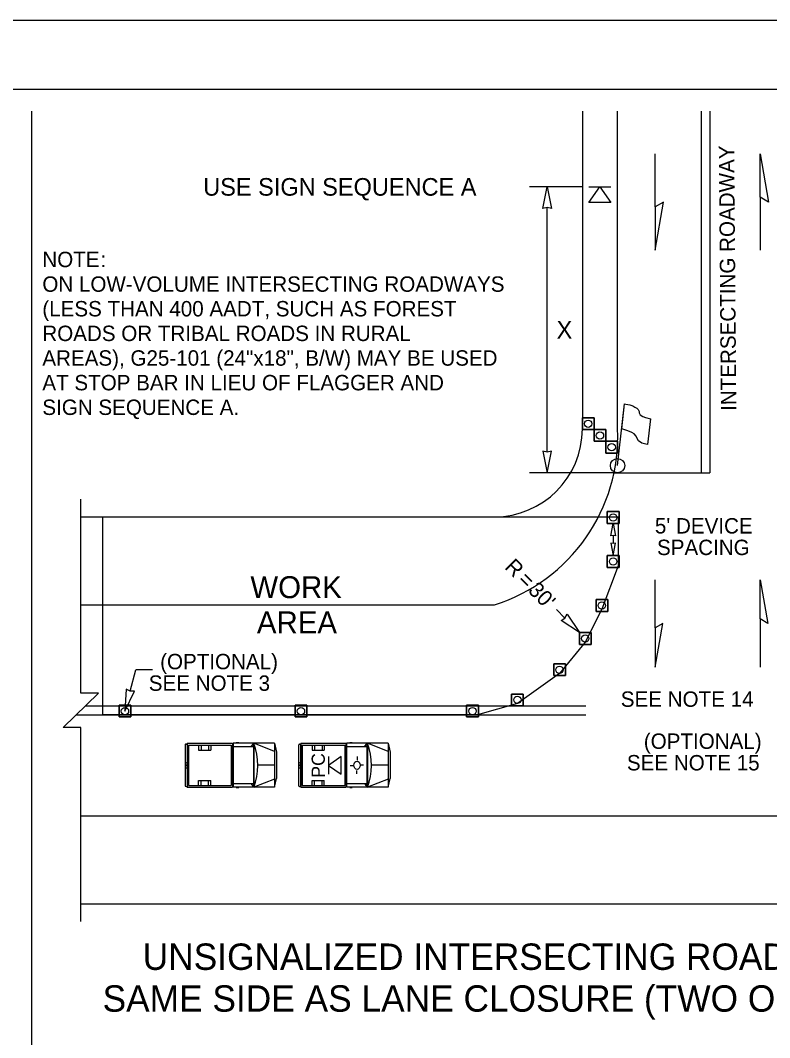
# Model space of a CAD drawing. Extents: x 99999.1 to 100095.7, y 99995 to 100010.7.
# Drawn here: x 100025.2 to 100028.607, y 100006.062 to 100010.687 of the extents above; entities that cross this region are included whole.
import ezdxf

# ---------------------------------------------------------------- set-up
doc = ezdxf.new("R2010")
doc.units = 0
for name, color, linetype in [('RD_ED_ShoulderPavedEdge', 7, 'Continuous'), ('RD_MK_LineDblYellowCenter', 7, 'Continuous'), ('RD_MK_LineEdgeWhite', 7, 'Continuous'), ('RD_MK_LineStop', 7, 'Continuous'), ('SH_DE_DetailBody1Text', 7, 'Continuous'), ('SH_DE_DetailHeading2Text', 7, 'Continuous'), ('SH_GI_PlotLimits', 7, 'Continuous'), ('SH_GI_SheetBorder', 7, 'Continuous'), ('TR_WZ_FlaggingStation', 7, 'Continuous'), ('TR_WZ_MotoristVehicle', 7, 'Continuous'), ('TR_WZ_PortableSignMountBlk-Org', 7, 'Continuous'), ('TR_WZ_PortableSignMountBlk-Wht', 7, 'Continuous'), ('TR_WZ_TrafficCone', 7, 'Continuous'), ('TR_WZ_WorkAreaLabel', 7, 'Continuous'), ('TR_WZ_WorkZoneDetails', 7, 'Continuous'), ('TR_WZ_WorkZoneTextCurrent', 7, 'Continuous')]:
    doc.layers.add(name, color=color, linetype=linetype)

msp = doc.modelspace()

# ---------------------------------------------------------------- linework, layer by layer
at = {"layer": 'RD_ED_ShoulderPavedEdge'}
for p, q in [((100025.475, 100008.4304), (100027.355, 100008.4304)), ((100025.475, 100006.6704), (100030.275, 100006.6704))]:
    msp.add_line(p, q, dxfattribs=at)
msp.add_lwpolyline([(100027.755, 100010.275), (100027.755, 100008.8304)], dxfattribs=at)
msp.add_arc((100027.355, 100008.8304), 0.4, 270, 0, dxfattribs=at)
at = {"layer": 'RD_MK_LineDblYellowCenter'}
for p, q in [((100028.295, 100010.275), (100028.295, 100008.6304)), ((100028.335, 100010.275), (100028.335, 100008.6304)), ((100025.4957, 100007.5704), (100027.7712, 100007.5704)), ((100025.4543, 100007.5305), (100027.7712, 100007.5305))]:
    msp.add_line(p, q, dxfattribs=at)
at = {"layer": 'RD_MK_LineEdgeWhite'}
for p, q in [((100027.915, 100008.8304), (100027.915, 100010.275)), ((100025.475, 100008.0305), (100027.355, 100008.0305)), ((100025.475, 100007.0704), (100030.275, 100007.0704))]:
    msp.add_line(p, q, dxfattribs=at)
msp.add_arc((100027.1158, 100008.7939), 0.8, 287.3948, 2.6212, dxfattribs=at)
at = {"layer": 'RD_MK_LineStop'}
msp.add_line((100027.899, 100008.6304), (100028.335, 100008.6304), dxfattribs=at)
at = {"layer": 'SH_GI_PlotLimits'}
msp.add_lwpolyline([(100019.0625, 99999.6875), (100036.0625, 99999.6875), (100036.0625, 100010.6875), (100019.0625, 100010.6875)], close=True, dxfattribs=at)
at = {"layer": 'SH_GI_SheetBorder'}
msp.add_line((100020, 100010.375), (100035.75, 100010.375), dxfattribs=at)
at = {"layer": 'TR_WZ_FlaggingStation'}
for p, q in [((100027.915, 100008.6629), (100027.9471, 100008.9439)), ((100027.934, 100008.8299), (100027.9471, 100008.9442)), ((100028.065, 100008.8764), (100028.0517, 100008.7592)), ((100027.934, 100008.8299), (100027.934, 100008.8299))]:
    msp.add_line(p, q, dxfattribs=at)
for points in [[(100027.9471, 100008.9442), (100027.9528, 100008.9429), (100027.9707, 100008.9395), (100027.9845, 100008.9353), (100027.9942, 100008.9292), (100028.0027, 100008.9245), (100028.0084, 100008.9177), (100028.0126, 100008.9098), (100028.0131, 100008.9037), (100028.0185, 100008.8944), (100028.0293, 100008.887), (100028.0417, 100008.8818), (100028.065, 100008.8764)], [(100028.0517, 100008.7592), (100028.0436, 100008.7606), (100028.0259, 100008.7653), (100028.0103, 100008.7758), (100028.0037, 100008.7863), (100027.9998, 100008.7966), (100027.9907, 100008.8075), (100027.9798, 100008.8137), (100027.9624, 100008.8208), (100027.934, 100008.8299)]]:
    msp.add_lwpolyline(points, dxfattribs=at)
msp.add_circle((100027.915, 100008.6629), 0.0325, dxfattribs=at)
at = {"layer": 'TR_WZ_MotoristVehicle'}
for p, q in [((100025.9487, 100007.3911), (100025.9487, 100007.2098)), ((100025.9532, 100007.3972), (100025.9577, 100007.3972)), ((100025.9577, 100007.3972), (100025.9577, 100007.2037)), ((100025.9584, 100007.4005), (100026.1641, 100007.4005)), ((100025.9584, 100007.4005), (100025.9584, 100007.2005)), ((100025.9642, 100007.3925), (100025.9642, 100007.2084)), ((100025.9642, 100007.3925), (100026.1582, 100007.3925)), ((100026.0106, 100007.3925), (100026.0106, 100007.3695)), ((100026.0106, 100007.3695), (100026.0655, 100007.3695)), ((100026.0215, 100007.3925), (100026.0215, 100007.3695)), ((100026.0556, 100007.3925), (100026.0556, 100007.3695)), ((100026.0655, 100007.3925), (100026.0655, 100007.3695)), ((100026.1582, 100007.3925), (100026.1582, 100007.2084)), ((100026.1641, 100007.4005), (100026.1641, 100007.2005)), ((100026.1668, 100007.4005), (100026.1668, 100007.2005)), ((100026.3557, 100007.4005), (100026.1668, 100007.4005)), ((100026.2596, 100007.385), (100026.1668, 100007.385)), ((100026.1926, 100007.4033), (100026.1813, 100007.4033)), ((100026.2596, 100007.4005), (100026.2475, 100007.385)), ((100026.2596, 100007.4005), (100026.2596, 100007.2005)), ((100026.2613, 100007.4005), (100026.2613, 100007.2005)), ((100026.3557, 100007.3638), (100026.2613, 100007.4005)), ((100026.3557, 100007.4005), (100026.3557, 100007.2005)), ((100026.3557, 100007.4005), (100026.365, 100007.3601)), ((100026.365, 100007.3601), (100026.365, 100007.2408)), ((100026.465, 100007.3911), (100026.465, 100007.2098)), ((100026.4695, 100007.3972), (100026.4739, 100007.3972)), ((100026.4739, 100007.3972), (100026.4739, 100007.2037)), ((100026.4746, 100007.4005), (100026.6803, 100007.4005)), ((100026.4746, 100007.4005), (100026.4746, 100007.2005)), ((100026.4805, 100007.3925), (100026.4805, 100007.2084)), ((100026.4805, 100007.3925), (100026.6745, 100007.3925)), ((100026.5268, 100007.3925), (100026.5268, 100007.3695)), ((100026.5268, 100007.3695), (100026.5818, 100007.3695)), ((100026.5378, 100007.3925), (100026.5378, 100007.3695)), ((100026.5718, 100007.3925), (100026.5718, 100007.3695)), ((100026.5818, 100007.3925), (100026.5818, 100007.3695)), ((100026.6745, 100007.3925), (100026.6745, 100007.2084)), ((100026.6803, 100007.4005), (100026.6803, 100007.2005)), ((100026.6831, 100007.4005), (100026.6831, 100007.2005)), ((100026.872, 100007.4005), (100026.6831, 100007.4005)), ((100026.7758, 100007.385), (100026.6831, 100007.385)), ((100026.7089, 100007.4033), (100026.6975, 100007.4033)), ((100026.7758, 100007.4005), (100026.7638, 100007.385)), ((100026.7758, 100007.4005), (100026.7758, 100007.2005)), ((100026.7775, 100007.4005), (100026.7775, 100007.2005)), ((100026.872, 100007.3638), (100026.7775, 100007.4005)), ((100026.872, 100007.4005), (100026.872, 100007.2005)), ((100026.872, 100007.4005), (100026.8813, 100007.3601)), ((100026.8813, 100007.3601), (100026.8813, 100007.2408)), ((100025.9487, 100007.3145), (100025.9577, 100007.3108)), ((100026.465, 100007.3145), (100026.4739, 100007.3108)), ((100026.7305, 100007.3401), (100026.7305, 100007.3239)), ((100025.9487, 100007.2864), (100025.9577, 100007.2901)), ((100025.9511, 100007.3005), (100025.9553, 100007.3005)), ((100025.9532, 100007.3033), (100025.9532, 100007.2976)), ((100026.3557, 100007.3005), (100026.2798, 100007.3005)), ((100026.465, 100007.2864), (100026.4739, 100007.2901)), ((100026.4674, 100007.3005), (100026.4715, 100007.3005)), ((100026.4695, 100007.3033), (100026.4695, 100007.2976)), ((100026.6996, 100007.2997), (100026.7145, 100007.3001)), ((100026.7164, 100007.3001), (100026.7164, 100007.3001)), ((100026.7298, 100007.262), (100026.7301, 100007.277)), ((100026.7606, 100007.3006), (100026.748, 100007.3005)), ((100026.872, 100007.3005), (100026.7961, 100007.3005)), ((100026.0106, 100007.2084), (100026.0106, 100007.2314)), ((100026.0106, 100007.2314), (100026.0655, 100007.2314)), ((100026.0215, 100007.2084), (100026.0215, 100007.2314)), ((100026.0556, 100007.2084), (100026.0556, 100007.2314)), ((100026.0655, 100007.2084), (100026.0655, 100007.2314)), ((100026.3557, 100007.2371), (100026.2613, 100007.2005)), ((100026.3557, 100007.2005), (100026.365, 100007.2408)), ((100026.5268, 100007.2084), (100026.5268, 100007.2314)), ((100026.5268, 100007.2314), (100026.5818, 100007.2314)), ((100026.5378, 100007.2084), (100026.5378, 100007.2314)), ((100026.5718, 100007.2084), (100026.5718, 100007.2314)), ((100026.5818, 100007.2084), (100026.5818, 100007.2314)), ((100026.872, 100007.2371), (100026.7775, 100007.2005)), ((100026.872, 100007.2005), (100026.8813, 100007.2408)), ((100025.9532, 100007.2037), (100025.9577, 100007.2037)), ((100025.9584, 100007.2005), (100026.1641, 100007.2005)), ((100025.9642, 100007.2084), (100026.1582, 100007.2084)), ((100026.2596, 100007.216), (100026.1668, 100007.216)), ((100026.3557, 100007.2005), (100026.1668, 100007.2005)), ((100026.1926, 100007.1976), (100026.1813, 100007.1976)), ((100026.2496, 100007.216), (100026.2596, 100007.2005)), ((100026.4695, 100007.2037), (100026.4739, 100007.2037)), ((100026.4746, 100007.2005), (100026.6803, 100007.2005)), ((100026.4805, 100007.2084), (100026.6745, 100007.2084)), ((100026.7758, 100007.216), (100026.6831, 100007.216)), ((100026.872, 100007.2005), (100026.6831, 100007.2005)), ((100026.7089, 100007.1976), (100026.6975, 100007.1976)), ((100026.7659, 100007.216), (100026.7758, 100007.2005))]:
    msp.add_line(p, q, dxfattribs=at)
for centre, major_axis, start_param, end_param in [((100025.9532, 100007.3911), (0, 0.0061), 6.283185, 7.853982), ((100026.1263, 100007.3004), (0, 0.2099), 4.215852, 5.209111), ((100026.4695, 100007.3911), (0, 0.0061), 6.283185, 7.853982), ((100026.6426, 100007.3004), (0, 0.2099), 4.215852, 5.209111), ((100025.9532, 100007.2098), (0, -0.0061), 4.712389, 6.283185), ((100026.4695, 100007.2098), (0, -0.0061), 4.712389, 6.283185)]:
    msp.add_ellipse(centre, major_axis=major_axis, ratio=0.73155, start_param=start_param, end_param=end_param, dxfattribs=at)
for centre, major_axis in [((100026.7305, 100007.3005), (0, -0.0193)), ((100025.9532, 100007.3005), (0, -0.00282)), ((100026.4695, 100007.3005), (0, -0.00282))]:
    msp.add_ellipse(centre, major_axis=major_axis, ratio=0.73155, dxfattribs=at)
at = {"layer": 'TR_WZ_PortableSignMountBlk-Org'}
msp.add_line((100027.785, 100009.9304), (100027.885, 100009.9304), dxfattribs=at)
msp.add_lwpolyline([(100027.8349, 100009.9304), (100027.885, 100009.8586), (100027.785, 100009.8586)], close=True, dxfattribs=at)
at = {"layer": 'TR_WZ_PortableSignMountBlk-Wht'}
msp.add_line((100026.6007, 100007.3404), (100026.6007, 100007.2604), dxfattribs=at)
msp.add_lwpolyline([(100026.6007, 100007.3004), (100026.6581, 100007.2604), (100026.6581, 100007.3404)], close=True, dxfattribs=at)
at = {"layer": 'TR_WZ_TrafficCone'}
for points in [[(100027.8083, 100008.8803), (100027.8083, 100008.827), (100027.755, 100008.827), (100027.755, 100008.8803), (100027.8083, 100008.8803)], [(100027.755, 100008.8803), (100027.755, 100008.827), (100027.8083, 100008.827), (100027.8083, 100008.8803), (100027.755, 100008.8803)], [(100027.8617, 100008.827), (100027.8617, 100008.7736), (100027.8083, 100008.7736), (100027.8083, 100008.827), (100027.8617, 100008.827)], [(100027.8083, 100008.827), (100027.8083, 100008.7736), (100027.8617, 100008.7736), (100027.8617, 100008.827), (100027.8083, 100008.827)], [(100027.915, 100008.7736), (100027.915, 100008.7203), (100027.8617, 100008.7203), (100027.8617, 100008.7736), (100027.915, 100008.7736)], [(100027.8617, 100008.7736), (100027.8617, 100008.7203), (100027.915, 100008.7203), (100027.915, 100008.7736), (100027.8617, 100008.7736)], [(100027.8684, 100008.4538), (100027.9217, 100008.4538), (100027.9217, 100008.4005), (100027.8684, 100008.4005), (100027.8684, 100008.4538)], [(100027.8684, 100008.4005), (100027.9217, 100008.4005), (100027.9217, 100008.4538), (100027.8684, 100008.4538), (100027.8684, 100008.4005)], [(100027.8684, 100008.2538), (100027.9217, 100008.2538), (100027.9217, 100008.2005), (100027.8684, 100008.2005), (100027.8684, 100008.2538)], [(100027.8684, 100008.2005), (100027.9217, 100008.2005), (100027.9217, 100008.2538), (100027.8684, 100008.2538), (100027.8684, 100008.2005)], [(100027.8173, 100008.0538), (100027.8707, 100008.0538), (100027.8707, 100008.0005), (100027.8173, 100008.0005), (100027.8173, 100008.0538)], [(100027.8173, 100008.0005), (100027.8707, 100008.0005), (100027.8707, 100008.0538), (100027.8173, 100008.0538), (100027.8173, 100008.0005)], [(100027.7417, 100007.9038), (100027.795, 100007.9038), (100027.795, 100007.8505), (100027.7417, 100007.8505), (100027.7417, 100007.9038)], [(100027.7417, 100007.8505), (100027.795, 100007.8505), (100027.795, 100007.9038), (100027.7417, 100007.9038), (100027.7417, 100007.8505)], [(100027.6247, 100007.7615), (100027.6781, 100007.7615), (100027.6781, 100007.7082), (100027.6247, 100007.7082), (100027.6247, 100007.7615)], [(100027.6247, 100007.7082), (100027.6781, 100007.7082), (100027.6781, 100007.7615), (100027.6247, 100007.7615), (100027.6247, 100007.7082)], [(100027.433, 100007.6247), (100027.4864, 100007.6247), (100027.4864, 100007.5714), (100027.433, 100007.5714), (100027.433, 100007.6247)], [(100027.433, 100007.5714), (100027.4864, 100007.5714), (100027.4864, 100007.6247), (100027.433, 100007.6247), (100027.433, 100007.5714)], [(100025.649, 100007.5738), (100025.7024, 100007.5738), (100025.7024, 100007.5205), (100025.649, 100007.5205), (100025.649, 100007.5738)], [(100025.649, 100007.5205), (100025.7024, 100007.5205), (100025.7024, 100007.5738), (100025.649, 100007.5738), (100025.649, 100007.5205)], [(100026.449, 100007.5738), (100026.5024, 100007.5738), (100026.5024, 100007.5205), (100026.449, 100007.5205), (100026.449, 100007.5738)], [(100026.449, 100007.5205), (100026.5024, 100007.5205), (100026.5024, 100007.5738), (100026.449, 100007.5738), (100026.449, 100007.5205)], [(100027.229, 100007.5738), (100027.2824, 100007.5738), (100027.2824, 100007.5205), (100027.229, 100007.5205), (100027.229, 100007.5738)], [(100027.229, 100007.5205), (100027.2824, 100007.5205), (100027.2824, 100007.5738), (100027.229, 100007.5738), (100027.229, 100007.5205)]]:
    msp.add_lwpolyline(points, dxfattribs=at)
for centre in [(100027.7817, 100008.8536), (100027.835, 100008.8003), (100027.8883, 100008.747), (100027.895, 100008.4271), (100027.895, 100008.2271), (100027.844, 100008.0271), (100027.7683, 100007.8771), (100027.6514, 100007.7349), (100027.4597, 100007.598), (100025.6757, 100007.5471), (100026.4757, 100007.5471), (100027.2557, 100007.5471)]:
    msp.add_circle(centre, 0.0167, dxfattribs=at)
at = {"layer": 'TR_WZ_WorkZoneDetails'}
for p, q in [((100025.25, 100010.275), (100025.25, 100001.6859)), ((100028.0855, 100009.8393), (100028.0855, 100010.0804)), ((100027.755, 100009.9304), (100027.515, 100009.9304)), ((100028.5627, 100009.8839), (100028.5627, 100009.6428)), ((100027.595, 100008.7242), (100027.595, 100009.8367)), ((100027.899, 100008.6304), (100027.515, 100008.6304)), ((100027.8951, 100008.3459), (100027.8951, 100008.3083)), ((100028.0855, 100007.9255), (100028.0855, 100008.1445)), ((100027.6754, 100007.9701), (100027.637, 100008.0085)), ((100028.5627, 100007.9659), (100028.5627, 100007.7469)), ((100025.6993, 100007.6378), (100025.7245, 100007.7352)), ((100025.8007, 100007.7352), (100025.7245, 100007.7352))]:
    msp.add_line(p, q, dxfattribs=at)
for points in [[(100028.5627, 100010.0804), (100028.6013, 100009.8616), (100028.5627, 100009.8839)], [(100027.595, 100009.9304), (100027.6143, 100009.8322), (100027.595, 100009.8367), (100027.5757, 100009.8322)], [(100028.0855, 100009.6428), (100028.124, 100009.8616), (100028.0855, 100009.8393)], [(100027.595, 100008.6304), (100027.6143, 100008.7287), (100027.595, 100008.7242), (100027.5757, 100008.7287)], [(100027.9183, 100008.4304), (100027.9183, 100008.2071), (100027.844, 100008.0105), (100027.7683, 100007.8605), (100027.7683, 100007.8605), (100027.7683, 100007.8605), (100027.6514, 100007.7182), (100027.6514, 100007.7182), (100027.6514, 100007.7182), (100027.4597, 100007.5814), (100027.279, 100007.5305), (100026.499, 100007.5305), (100025.699, 100007.5305), (100025.575, 100007.5305), (100025.575, 100008.4304)], [(100027.895, 100008.4005), (100027.9063, 100008.3433), (100027.895, 100008.3459), (100027.8838, 100008.3433)], [(100027.8951, 100008.2538), (100027.9063, 100008.3109), (100027.8951, 100008.3083), (100027.8839, 100008.3109)], [(100028.5627, 100008.1445), (100028.5977, 100007.9457), (100028.5627, 100007.9659)], [(100027.7417, 100007.9038), (100027.6586, 100007.9597), (100027.6754, 100007.9701), (100027.6858, 100007.987)], [(100028.0855, 100007.7469), (100028.1205, 100007.9457), (100028.0855, 100007.9255)], [(100025.6757, 100007.5471), (100025.719, 100007.6374), (100025.6992, 100007.6379), (100025.6817, 100007.6471)]]:
    msp.add_lwpolyline(points, close=True, dxfattribs=at)
msp.add_lwpolyline([(100025.475, 100006.5905), (100025.475, 100007.473), (100025.395, 100007.473), (100025.555, 100007.6279), (100025.475, 100007.6279), (100025.475, 100008.5105)], dxfattribs=at)

# ---------------------------------------------------------------- texts
at = {"layer": 'SH_DE_DetailBody1Text'}
msp.add_text('INTERSECTING ROADWAY', height=0.07, rotation=90.4626, dxfattribs=at).set_placement((100028.455, 100008.9122))
at = {"layer": 'SH_DE_DetailHeading2Text'}
for s, p in [('UNSIGNALIZED INTERSECTING ROADWAY DETAIL', (100025.7563, 100006.3705)), ('SAME SIDE AS LANE CLOSURE (TWO OPEN LANES)', (100025.5738, 100006.1804))]:
    msp.add_text(s, height=0.12, rotation=360, dxfattribs=at).set_placement(p)
at = {"layer": 'TR_WZ_MotoristVehicle'}
msp.add_text('PC', height=0.06, rotation=90, dxfattribs=at).set_placement((100026.5843, 100007.2444))
at = {"layer": 'TR_WZ_WorkAreaLabel'}
for s, p in [('WORK', (100026.2458, 100008.0605)), ('AREA', (100026.2754, 100007.9004))]:
    msp.add_text(s, height=0.1, dxfattribs=at).set_placement(p)
at = {"layer": 'TR_WZ_WorkZoneDetails'}
for s, p in [('NOTE', (100025.3, 100009.5654)), (':', (100025.5641, 100009.5654)), ('ON LOW-VOLUME INTERSECTING ROADWAYS ', (100025.3, 100009.4534)), ('(LESS THAN 400 AADT, SUCH AS FOREST ', (100025.3, 100009.3414)), ('ROADS OR TRIBAL ROADS IN RURAL ', (100025.3, 100009.2294)), ('AREAS), G25-101 (24"x18", B/W) MAY BE USED ', (100025.3, 100009.1174)), ('AT STOP BAR IN LIEU OF FLAGGER AND ', (100025.3, 100009.0054)), ('SIGN SEQUENCE A.', (100025.3, 100008.8934))]:
    msp.add_text(s, height=0.07, dxfattribs=at).set_placement(p)
at = {"layer": 'TR_WZ_WorkZoneTextCurrent'}
for s, height, p in [('USE SIGN SEQUENCE A', 0.08, (100026.0313, 100009.8904)), ('X', 0.08, (100027.6379, 100009.2404)), ("5' DEVICE", 0.07, (100028.0848, 100008.3544)), ('SPACING', 0.07, (100028.0944, 100008.2564)), ('(OPTIONAL)', 0.07, (100025.8355, 100007.7372)), ('SEE NOTE 3', 0.07, (100025.7838, 100007.6392)), ('SEE NOTE 14', 0.07, (100027.9297, 100007.5665)), ('(OPTIONAL)', 0.07, (100028.0344, 100007.3753)), ('SEE NOTE 15', 0.07, (100027.9575, 100007.2773))]:
    msp.add_text(s, height=height, dxfattribs=at).set_placement(p)
for s, p in [('R', (100027.3982, 100008.1977)), ('=', (100027.4574, 100008.1386)), ("30'", (100027.5042, 100008.0917))]:
    msp.add_text(s, height=0.07, rotation=315, dxfattribs=at).set_placement(p)

doc.saveas('drawing.dxf')
